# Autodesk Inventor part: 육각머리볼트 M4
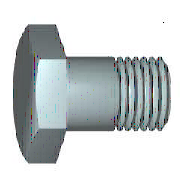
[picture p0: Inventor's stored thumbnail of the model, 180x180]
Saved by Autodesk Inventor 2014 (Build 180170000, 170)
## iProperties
IsCustomPart: 1
Created: 2012-02
Part Number: 육각머리볼트 M4
Material: 강철, 연강
Description: 6각 머리 볼트 및 6각 머리 나사
Document SubType Name: Modeling
Standard: KS B 1002
Designer: mduedu
Standards Organization: KS
Language: ko-KR
Size Designation: A + B M4 x 16
Categories: <MemberInstance><Categories><Category DisplayName="조임쇠" InternalName="e4da775c-781d-43d5-af7c-5136215cf5a6" Mnemonic="FSTN"><Category DisplayName="볼트" InternalN
Density: 1 g/cm^3
Appearance: 강철
Author: mduedu
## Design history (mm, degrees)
sketch "스케치1"
  geometry: L1 (0, 2.94)-(0, 2); L2 (2.1, 2)-(16, 2); L3 (16, 2)-(16, 0); L4 (16, 0)-(-0.4, 0); L5 (-3.68, 0)-(19.28, 0) reference; L6 (-0.4, 0)-(-0.4, 2.94); L7 (-0.4, 2.94)-(0, 2.94); L8 (2.1, 2)-(1.67, 2); L9 (1.67, 2)-(0, 2); L10 (0, -0.588)-(0, 3.528) reference
  constraints: 16 end point, 2 collinear, 2 perpendicular, 1 parallel
  dimensions: "d0" = 16 distance between parallel lines of L3 L1 (= NLG); "d1" = 13.9 distance from line of L2.start L3 (= GEL); "d2" = 4 diameter of L2 L4 (= GD); "d9" = 0.4001 distance between parallel lines of L6 L1 (computed from SD); "d10" = 5.88 diameter of L7 L4 (= SD2); "d13" = 0.42952 distance of L2.start L8.end (computed from GAL); "d14" = 4 diameter of L9 L4 (= BDM)
revolve "본체" sketch "스케치1" stored, may be unused: angle "d12" = 90 deg
sketch "스케치2"
  geometry: L1 (0, 4.041)-(3.5, 2.021); L2 (3.5, 2.021)-(3.5, -2.021); L3 (3.5, -2.021)-(0, -4.041); L4 (0, -4.041)-(-3.5, -2.021); L5 (-3.5, -2.021)-(-3.5, 2.021); L6 (-3.5, 2.021)-(0, 4.041); 2 further points
  constraints: 12 end point, 1 coincident, 1 vertical, 11 other
  dimensions: "d11" = 7 distance between parallel lines of L5 L2 (= SW)
extrude "머리" join sketch "스케치2" distance "d3" = 2.4 (= KOH - SD); taper "d4" = 0 deg
sketch "스케치4"
  geometry: L1 (-2.8, 3.5)-(-2.8, 4.041); L2 (-2.8, 4.041)-(-2.487, 4.041); L3 (-2.487, 4.041)-(-2.8, 3.5); L4 (-3.28, 0)-(0.08, 0) reference; L5 (-0.4, 4.041)-(-2.8, 4.041) reference; L6 (-2.8, 2.021)-(-2.8, 4.041) reference
  constraints: 6 end point, 2 collinear, 1 perpendicular, 1 vertical
  dimensions: "d5" = 30 deg angle of L3 L1 (= ANG1); "d19" = 7 diameter of L1.start L4 (= SW0)
revolve "모따기1" sketch "스케치4" stored, may be unused: angle "d21" = 90 deg
workplane "Work Plane1"
body "Solid1"
feature "스레드" dims "d15" = 13.9 (= GEL), "d16" = 0
chamfer "모따기2" distance "d6" = 0.42941 (= -0.5 x SPD + 0.5 x GD); stored, may be unused: second distance "d7" = 0.42952 (computed from GUL), angle "d55" = 45 deg
other parameters: "NLG" = 16 [user parameter; used in 1 equation term], "GD" = 4 (= NND) [user parameter; used in 2 equation terms], "BDM" = 4 (= NND) [user parameter; used in 1 equation term], "KOH" = 2.8 [user parameter; used in 1 equation term], "GEL" = 13.9 [user parameter; used in 2 equation terms], "SW" = 7 [user parameter; used in 3 equation terms], "SW0" = 7 (= SW) [user parameter; used in 1 equation term], "SPD" = 3.14117 (= NND - 1.2269 x PTC) [user parameter; used in 1 equation term], "SD2" = 5.88 (= SDH) [user parameter; used in 1 equation term], "SD" = 0.4 [user parameter; used in 2 equation terms], "ANG1" = 30 deg [user parameter; used in 1 equation term], "GAL" = 0.42941 (= 0.61345 x PTC) [user parameter; used in 1 equation term], "GUL" = 0.42941 (= 0.61345 x PTC) [user parameter; used in 1 equation term], "d8" = 0, "RR" = 0.2 [user parameter], "d57" = 0, "d58" = 0, "TPU" = 14.28571 (computed from PTC) [user parameter], "GD1" = 3.14117 (= THREADDIA - 1.2269 x PTC) [user parameter], "THREADDIA" = 4 [user parameter; used in 1 equation term], "SDH" = 5.88 [user parameter; used in 1 equation term], "SDHG" = 2.1 [user parameter], "TOA" = 30 deg [user parameter], "PTC" = 0.7 [user parameter; used in 5 equation terms], "NND" = 4 [user parameter; used in 3 equation terms], "E0" = 8.085 (= 1.155 x SW) [user parameter]
